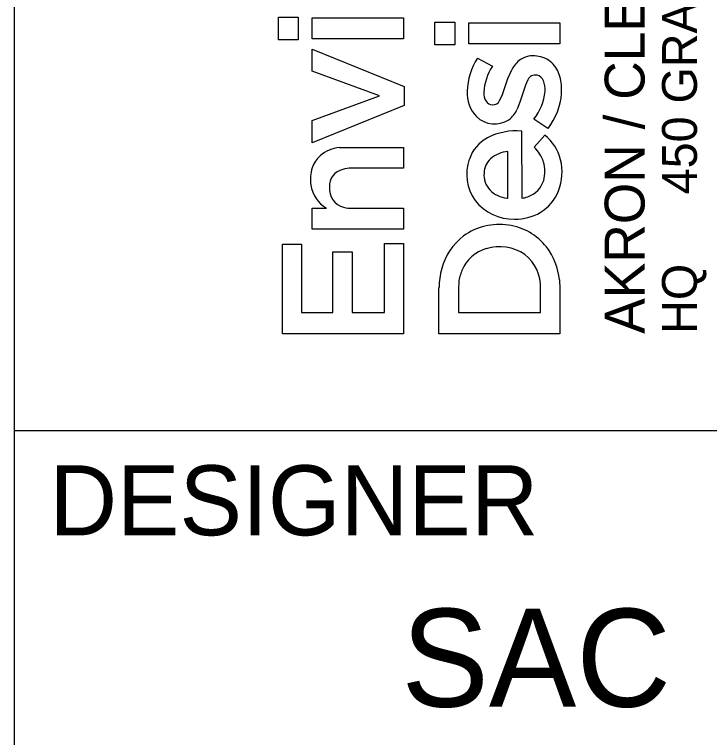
# Model space of a CAD drawing. Extents: x -0.4 to 34, y 0 to 22.
# Drawn here: x 32 to 32.993, y 2.061 to 3.094 of the extents above; entities that cross this region are included whole.
import ezdxf

# ---------------------------------------------------------------- set-up
doc = ezdxf.new("R2010")
doc.units = 0
doc.layers.add('SH_Border', color=7, linetype='Continuous')
doc.layers.add('SH_Cut_Line', color=7, linetype='Continuous')

msp = doc.modelspace()

# ---------------------------------------------------------------- linework, layer by layer
at = {"layer": 'SH_Border'}
for p, q in [((32.3771, 3.0582), (32.3771, 3.0903)), ((32.3771, 3.0903), (32.4054, 3.0903)), ((32.4054, 3.0903), (32.4054, 3.0582)), ((32.4254, 3.0594), (32.4254, 3.0893)), ((32.4254, 3.0893), (32.5557, 3.0893)), ((32.5557, 3.0893), (32.5557, 3.0594)), ((32.6005, 3.0511), (32.6005, 3.0832)), ((32.6005, 3.0832), (32.6289, 3.0832)), ((32.6289, 3.0832), (32.6289, 3.0511)), ((32.6489, 3.0523), (32.6489, 3.0822)), ((32.6489, 3.0822), (32.7792, 3.0822)), ((32.7792, 3.0822), (32.7792, 3.0523)), ((32.5557, 3.0594), (32.4254, 3.0594)), ((32.4054, 3.0582), (32.3771, 3.0582)), ((32.6289, 3.0511), (32.6005, 3.0511)), ((32.7792, 3.0523), (32.6489, 3.0523)), ((32.4254, 3.0133), (32.4254, 3.0446)), ((32.4254, 3.0446), (32.5567, 2.9913)), ((32.6615, 3.0321), (32.6827, 3.0203)), ((32.5212, 2.978), (32.4254, 3.0133)), ((32.7048, 3.0026), (32.7104, 3.0153)), ((32.6967, 2.9787), (32.7048, 3.0026)), ((32.7334, 3.001), (32.7298, 2.9933)), ((32.5567, 2.9913), (32.5567, 2.9644)), ((32.7298, 2.9933), (32.7221, 2.9688)), ((32.4254, 2.9429), (32.5212, 2.978)), ((32.693, 2.9712), (32.6967, 2.9787)), ((32.7221, 2.9688), (32.7182, 2.9592)), ((32.5567, 2.9644), (32.4254, 2.9109)), ((32.4254, 2.9109), (32.4254, 2.9429)), ((32.7621, 2.9314), (32.742, 2.9447)), ((32.7245, 2.9275), (32.7246, 2.8319)), ((32.7423, 2.9046), (32.7577, 2.922)), ((32.4644, 2.904), (32.4729, 2.9044)), ((32.4729, 2.9044), (32.5557, 2.9044)), ((32.5557, 2.9044), (32.5557, 2.8746)), ((32.7049, 2.8318), (32.7049, 2.8983)), ((32.5557, 2.8746), (32.4814, 2.8746)), ((32.7036, 2.8317), (32.7049, 2.8318)), ((32.4254, 2.7875), (32.4254, 2.8173)), ((32.4254, 2.8173), (32.4455, 2.8173)), ((32.4822, 2.8173), (32.5557, 2.8173)), ((32.5557, 2.8173), (32.5557, 2.7876)), ((32.5557, 2.7876), (32.4254, 2.7875)), ((32.383, 2.6379), (32.383, 2.766)), ((32.383, 2.766), (32.4101, 2.766)), ((32.4101, 2.766), (32.4101, 2.6683)), ((32.5286, 2.6683), (32.5286, 2.7672)), ((32.5286, 2.7672), (32.5557, 2.7672)), ((32.5557, 2.7672), (32.5557, 2.6379)), ((32.455, 2.6683), (32.455, 2.7549)), ((32.455, 2.7549), (32.4822, 2.7549)), ((32.4822, 2.7549), (32.4822, 2.6683)), ((32.6347, 2.7118), (32.6341, 2.7023)), ((32.7785, 2.715), (32.7792, 2.7021)), ((32.6064, 2.638), (32.6064, 2.704)), ((32.6341, 2.7023), (32.6341, 2.6684)), ((32.7515, 2.6683), (32.7515, 2.7024)), ((32.7792, 2.7021), (32.7792, 2.638)), ((32.4101, 2.6683), (32.455, 2.6683)), ((32.4822, 2.6683), (32.5286, 2.6683)), ((32.6341, 2.6684), (32.7515, 2.6683)), ((32.5557, 2.6379), (32.383, 2.6379)), ((32.7792, 2.638), (32.6064, 2.638))]:
    msp.add_line(p, q, dxfattribs=at)
for points in [[(32.3771, 3.0582), (32.3771, 3.0903), (32.4054, 3.0903), (32.4054, 3.0582)], [(32.4254, 3.0594), (32.4254, 3.0893), (32.5557, 3.0893), (32.5557, 3.0594)], [(32.6005, 3.0511), (32.6005, 3.0832), (32.6289, 3.0832), (32.6289, 3.0511)], [(32.6489, 3.0523), (32.6489, 3.0822), (32.7792, 3.0822), (32.7792, 3.0523)], [(32.4254, 2.9109), (32.4254, 2.9429), (32.5212, 2.978), (32.4254, 3.0133), (32.4254, 3.0446), (32.5567, 2.9913), (32.5567, 2.9644)], [(32.383, 2.6379), (32.383, 2.766), (32.4101, 2.766), (32.4101, 2.6683), (32.455, 2.6683), (32.455, 2.7549), (32.4822, 2.7549), (32.4822, 2.6683), (32.5286, 2.6683), (32.5286, 2.7672), (32.5557, 2.7672), (32.5557, 2.6379)]]:
    msp.add_lwpolyline(points, close=True, dxfattribs=at)
for points in [[(32.6615, 3.0321), (32.6827, 3.0203)], [(32.693, 2.9712), (32.6967, 2.9787), (32.7048, 3.0026), (32.7104, 3.0153)], [(32.7334, 3.001), (32.7298, 2.9933), (32.7221, 2.9688), (32.7182, 2.9592)], [(32.7621, 2.9314), (32.742, 2.9447)], [(32.7245, 2.9275), (32.7246, 2.8319)], [(32.7423, 2.9046), (32.7577, 2.922)], [(32.4644, 2.904), (32.4729, 2.9044), (32.5557, 2.9044), (32.5557, 2.8746), (32.4814, 2.8746)], [(32.7036, 2.8317), (32.7049, 2.8318), (32.7049, 2.8983)], [(32.4254, 2.7875), (32.4254, 2.8173), (32.4455, 2.8173)], [(32.4822, 2.8173), (32.5557, 2.8173), (32.5557, 2.7876), (32.4254, 2.7875)], [(32.7785, 2.715), (32.7792, 2.7021), (32.7792, 2.638), (32.6064, 2.638)], [(32.6347, 2.7118), (32.6341, 2.7023), (32.6341, 2.6684), (32.7515, 2.6683), (32.7515, 2.7024)], [(32.6064, 2.638), (32.6064, 2.704)]]:
    msp.add_lwpolyline(points, dxfattribs=at)
for centre, radius, start, end in [((32.7364, 2.9826), 0.0897, 146.531, 178.7571), ((32.7364, 2.9826), 0.0897, 146.531, 178.7571), ((32.7466, 2.9971), 0.0405, 125.5118, 153.4159), ((32.7466, 2.9971), 0.0405, 125.5118, 153.4159), ((32.7406, 3.0026), 0.0326, 80.1719, 122.5197), ((32.7406, 3.0026), 0.0326, 80.1719, 122.5197), ((32.7428, 2.9982), 0.0367, 47.7934, 84.6892), ((32.7428, 2.9982), 0.0367, 47.7934, 84.6892), ((32.7452, 2.9789), 0.0749, 146.5112, 176.9101), ((32.7452, 2.9789), 0.0749, 146.5112, 176.9101), ((32.7379, 2.9946), 0.0427, 14.9966, 46.2063), ((32.7379, 2.9946), 0.0427, 14.9966, 46.2063), ((32.7438, 2.9963), 0.0114, 76.6609, 155.7053), ((32.7438, 2.9963), 0.0114, 76.6609, 155.7053), ((32.744, 2.9951), 0.0126, 21.5098, 78.5262), ((32.744, 2.9951), 0.0126, 21.5098, 78.5262), ((32.7259, 2.9877), 0.0321, 354.5726, 22.068), ((32.7259, 2.9877), 0.0321, 354.5726, 22.068), ((32.7104, 2.9867), 0.0712, 355.8306, 15.3914), ((32.7104, 2.9867), 0.0712, 355.8306, 15.3914), ((32.6967, 2.9824), 0.0501, 177.5366, 222.7932), ((32.6967, 2.9824), 0.0501, 177.5366, 222.7932), ((32.6931, 2.9823), 0.0228, 178.4747, 211.0868), ((32.6931, 2.9823), 0.0228, 178.4747, 211.0868), ((32.6825, 2.9915), 0.0757, 321.811, 354.7969), ((32.6825, 2.9915), 0.0757, 321.811, 354.7969), ((32.6895, 2.9882), 0.0922, 321.9777, 355.8738), ((32.6895, 2.9882), 0.0922, 321.9777, 355.8738), ((32.6833, 2.9767), 0.0115, 212.2368, 268.3777), ((32.6833, 2.9767), 0.0115, 212.2368, 268.3777), ((32.6834, 2.9759), 0.0107, 267.716, 333.7337), ((32.6834, 2.9759), 0.0107, 267.716, 333.7337), ((32.681, 2.9758), 0.0408, 308.0877, 335.9874), ((32.681, 2.9758), 0.0408, 308.0877, 335.9874), ((32.686, 2.9753), 0.0375, 225.9854, 302.4797), ((32.686, 2.9753), 0.0375, 225.9854, 302.4797), ((32.7152, 2.8441), 0.0838, 83.615, 118.2876), ((32.7152, 2.8441), 0.0838, 83.615, 118.2876), ((32.7024, 2.8691), 0.0558, 118.8308, 160.6244), ((32.7024, 2.8691), 0.0558, 118.8308, 160.6244), ((32.7174, 2.8717), 0.0644, 13.5336, 51.3615), ((32.7174, 2.8717), 0.0644, 13.5336, 51.3615), ((32.4687, 2.8543), 0.0499, 94.9696, 130.2225), ((32.4687, 2.8543), 0.0499, 94.9696, 130.2225), ((32.7038, 2.8656), 0.0549, 19.0357, 45.4406), ((32.7038, 2.8656), 0.0549, 19.0357, 45.4406), ((32.7079, 2.8561), 0.0424, 94.008, 130.8817), ((32.7079, 2.8561), 0.0424, 94.008, 130.8817), ((32.4635, 2.8626), 0.0402, 132.2219, 161.6818), ((32.4635, 2.8626), 0.0402, 132.2219, 161.6818), ((32.7104, 2.8661), 0.0644, 160.5201, 215.7831), ((32.7104, 2.8661), 0.0644, 160.5201, 215.7831), ((32.7005, 2.8663), 0.0298, 132.9851, 177.179), ((32.7005, 2.8663), 0.0298, 132.9851, 177.179), ((32.7107, 2.8697), 0.047, 344.6059, 17.007), ((32.7107, 2.8697), 0.047, 344.6059, 17.007), ((32.7064, 2.8692), 0.0758, 339.3542, 13.3785), ((32.7064, 2.8692), 0.0758, 339.3542, 13.3785), ((32.4787, 2.8582), 0.056, 162.2736, 187.7919), ((32.4787, 2.8582), 0.056, 162.2736, 187.7919), ((32.4748, 2.8487), 0.025, 103.6865, 182.2187), ((32.4748, 2.8487), 0.025, 103.6865, 182.2187), ((32.4811, 2.8286), 0.046, 89.6049, 105.3284), ((32.4811, 2.8286), 0.046, 89.6049, 105.3284), ((32.7017, 2.865), 0.0311, 175.0013, 223.283), ((32.7017, 2.865), 0.0311, 175.0013, 223.283), ((32.7224, 2.8671), 0.035, 288.0077, 343.5508), ((32.7224, 2.8671), 0.035, 288.0077, 343.5508), ((32.4703, 2.858), 0.0476, 188.962, 238.7037), ((32.4703, 2.858), 0.0476, 188.962, 238.7037), ((32.4773, 2.8456), 0.0276, 175.5854, 255.1439), ((32.4773, 2.8456), 0.0276, 175.5854, 255.1439), ((32.7089, 2.8736), 0.0423, 225.0619, 262.7974), ((32.7089, 2.8736), 0.0423, 225.0619, 262.7974), ((32.7189, 2.8652), 0.0626, 300.9427, 338.7323), ((32.7189, 2.8652), 0.0626, 300.9427, 338.7323), ((32.7247, 2.8522), 0.0202, 269.7003, 294.8711), ((32.7247, 2.8522), 0.0202, 269.7003, 294.8711), ((32.7125, 2.8705), 0.0687, 217.7452, 271.6543), ((32.7125, 2.8705), 0.0687, 217.7452, 271.6543), ((32.4818, 2.8595), 0.0422, 254.0916, 270.5284), ((32.4818, 2.8595), 0.0422, 254.0916, 270.5284), ((32.7155, 2.8724), 0.0706, 269.2048, 300.3341), ((32.7155, 2.8724), 0.0706, 269.2048, 300.3341), ((32.6923, 2.7079), 0.0864, 81.194, 125.9984), ((32.6923, 2.7079), 0.0864, 81.194, 125.9984), ((32.6946, 2.7113), 0.0827, 37.8521, 82.402), ((32.6946, 2.7113), 0.0827, 37.8521, 82.402), ((32.6939, 2.7089), 0.0865, 127.2362, 165.148), ((32.6939, 2.7089), 0.0865, 127.2362, 165.148), ((32.6889, 2.7078), 0.054, 106.1881, 157.3861), ((32.6889, 2.7078), 0.054, 106.1881, 157.3861), ((32.6928, 2.6986), 0.0639, 55.6727, 107.2093), ((32.6928, 2.6986), 0.0639, 55.6727, 107.2093), ((32.6859, 2.7057), 0.0931, 5.7333, 37.304), ((32.6859, 2.7057), 0.0931, 5.7333, 37.304), ((32.6929, 2.705), 0.0587, 357.4662, 52.2665), ((32.6929, 2.705), 0.0587, 357.4662, 52.2665), ((32.7143, 2.7028), 0.1078, 164.7861, 179.3704), ((32.7143, 2.7028), 0.1078, 164.7861, 179.3704), ((32.6983, 2.7039), 0.0641, 157.3571, 172.9275), ((32.6983, 2.7039), 0.0641, 157.3571, 172.9275)]:
    msp.add_arc(centre, radius, start, end, dxfattribs=at)
at = {"layer": 'SH_Cut_Line'}
for p, q in [((32, 0.5), (32, 21.5)), ((32, 2.5), (33.5, 2.5))]:
    msp.add_line(p, q, dxfattribs=at)

# ---------------------------------------------------------------- texts
at = {"layer": 'SH_Border'}
for s, height, p in [('450 GRANT ST., AKRON, OH  44311', 0.049846, (32.9749, 2.8374)), ('AKRON / CLEVELAND / COLUMBUS', 0.056969, (32.9001, 2.638)), ('HQ ', 0.04985, (32.9749, 2.638))]:
    msp.add_text(s, height=height, rotation=90, dxfattribs=at).set_placement(p)
for s, height, p in [('DESIGNER', 0.1, (32.05, 2.35)), ('SAC', 0.14, (32.5528, 2.105))]:
    msp.add_text(s, height=height, dxfattribs=at).set_placement(p)

doc.saveas('drawing.dxf')
